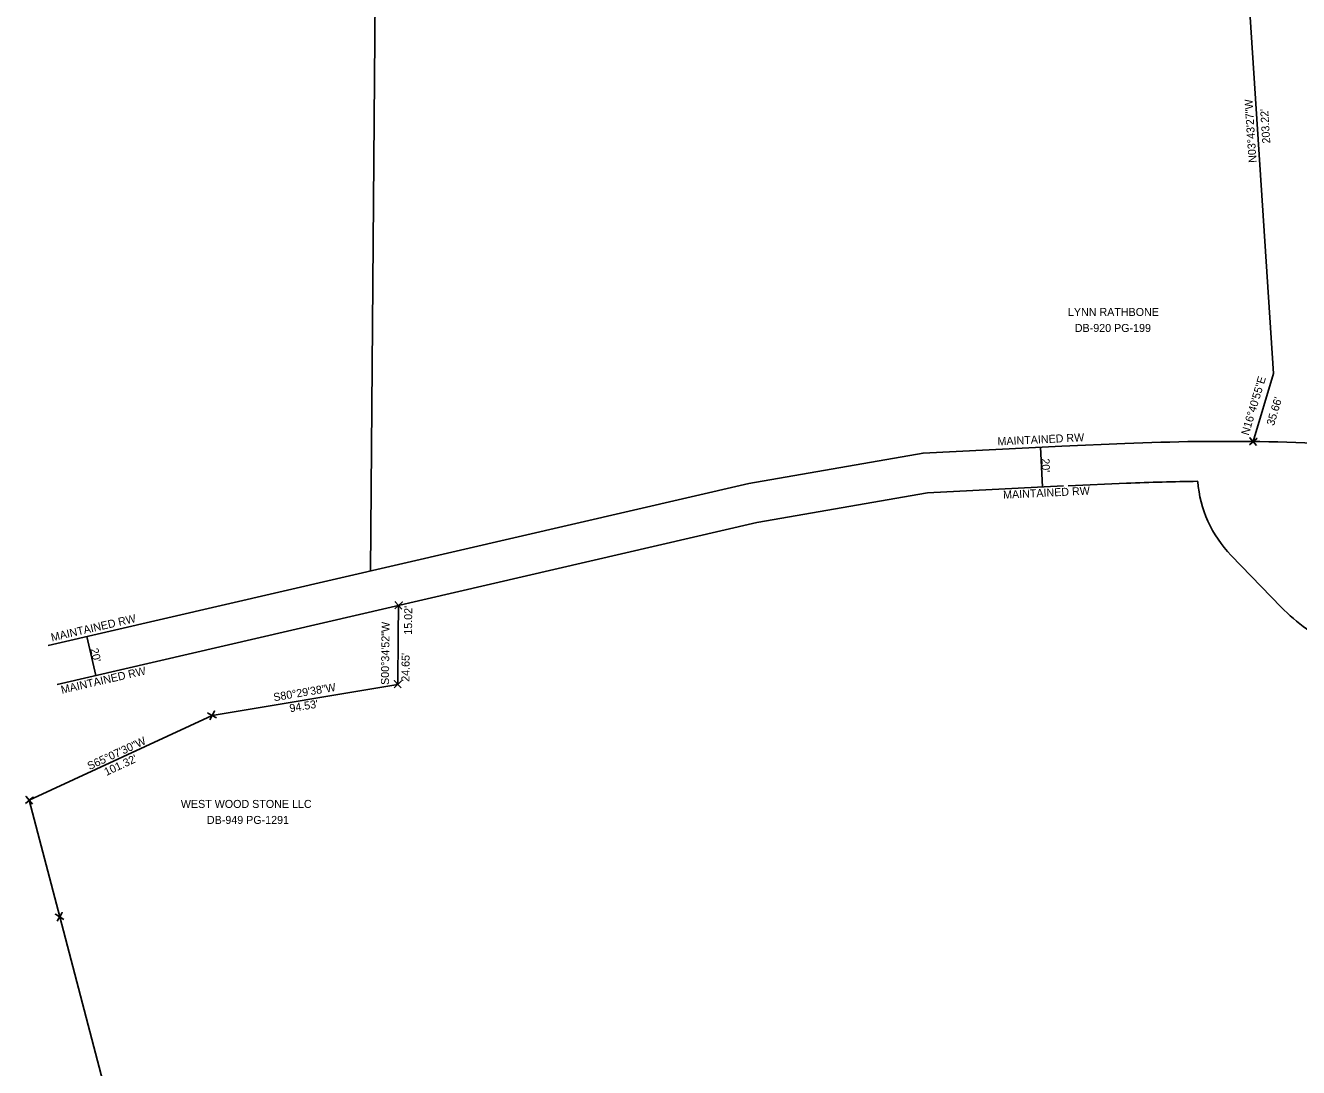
# Model space of a CAD drawing. Extents: x 831731 to 833706, y 722402 to 726085.
# Drawn here: x 831731 to 832371, y 723991 to 724515 of the extents above; entities that cross this region are included whole.
import ezdxf

# ---------------------------------------------------------------- set-up
doc = ezdxf.new("R2010")
doc.units = 0
for name, color, linetype in [('Exist Property Corner CELL', 7, 'Continuous'), ('Exist Property Line', 7, 'Continuous'), ('Exist Property Text', 7, 'Continuous'), ('Exist Right of Way Line', 7, 'Continuous'), ('Exist Right of Way Text', 7, 'Continuous'), ('Exist Right of Way Width CELL', 7, 'Continuous')]:
    doc.layers.add(name, color=color, linetype=linetype)

msp = doc.modelspace()

# ---------------------------------------------------------------- linework, layer by layer
at = {"layer": 'Exist Property Corner CELL'}
for p, q in [((832347.96, 724305.9), (832347.96, 724305.9)), ((831918.67, 724223.59), (831918.67, 724223.59)), ((831918.27, 724183.92), (831918.27, 724183.92)), ((831825.04, 724168.31), (831825.04, 724168.31)), ((831733.12, 724125.69), (831733.12, 724125.69)), ((831748.43, 724067.15), (831748.43, 724067.15))]:
    msp.add_line(p, q, dxfattribs=at)
for points in [[(832346.06, 724304.28), (832349.87, 724307.51), (832347.96, 724305.9), (832346.35, 724307.8), (832349.58, 724303.99)], [(831916.82, 724221.91), (831920.52, 724225.27), (831918.67, 724223.59), (831916.99, 724225.44), (831920.35, 724221.74)], [(831916.44, 724182.22), (831920.1, 724185.62), (831918.27, 724183.92), (831916.57, 724185.75), (831919.97, 724182.09)], [(831823.87, 724166.1), (831826.2, 724170.52), (831825.04, 724168.31), (831822.83, 724169.47), (831827.25, 724167.14)], [(831731.21, 724124.07), (831735.02, 724127.31), (831733.12, 724125.69), (831731.49, 724127.59), (831734.74, 724123.79)], [(831747.14, 724065), (831749.71, 724069.29), (831748.43, 724067.15), (831746.29, 724068.43), (831750.57, 724065.86)]]:
    msp.add_lwpolyline(points, dxfattribs=at)
at = {"layer": 'Exist Property Line'}
for p, q in [((831909.37, 724844.45), (831904.52, 724240.84)), ((832358.2, 724340.06), (832345, 724542.84)), ((832347.96, 724305.9), (832358.2, 724340.06)), ((831918.67, 724223.59), (831918.52, 724208.57)), ((831918.52, 724208.57), (831918.27, 724183.92)), ((831918.27, 724183.92), (831825.04, 724168.31)), ((831825.04, 724168.31), (831733.12, 724125.69)), ((831733.12, 724125.69), (831748.43, 724067.15)), ((831748.43, 724067.15), (832019.98, 723028.96))]:
    msp.add_line(p, q, dxfattribs=at)
at = {"layer": 'Exist Right of Way Line'}
for p, q in [((832251.85, 724303.55), (832283.49, 724304.91)), ((832254.96, 724283.66), (832284.35, 724284.93)), ((832336.9, 724248.71), (832362.08, 724222.76))]:
    msp.add_line(p, q, dxfattribs=at)
for points in [[(832251.79, 724303.55), (832182.16, 724300.12), (832094.68, 724284.84), (831742.62, 724203.38)], [(832252.77, 724283.57), (832184.38, 724280.21), (832098.66, 724265.24), (831747.13, 724183.9)]]:
    msp.add_lwpolyline(points, dxfattribs=at)
for centre, radius, start, end in [((832333.41, 723145.99), 1160, 85.31667, 92.46667), ((832333.41, 723145.99), 1140, 90.66701, 92.46667), ((832379.96, 724290.49), 60, 184.38299, 224.13333), ((832430.27, 724288.91), 95, 224.13333, 244.41667)]:
    msp.add_arc(centre, radius, start, end, dxfattribs=at)
at = {"layer": 'Exist Right of Way Width CELL'}
for p, q in [((832242.08, 724283.08), (832241.16, 724303.06)), ((831766.63, 724188.41), (831762.12, 724207.89))]:
    msp.add_line(p, q, dxfattribs=at)
for points in [[(832241.16, 724303.02), (832241.17, 724302.77), (832241.04, 724302.99)], [(831762.12, 724207.89), (831762.18, 724207.64), (831762.01, 724207.83)]]:
    msp.add_lwpolyline(points, dxfattribs=at)

# ---------------------------------------------------------------- texts
at = {"layer": 'Exist Property Text'}
for s, rotation, p in [('N03°43\'27"W', 93.72403, (832349.7, 724446.06)), ("203.22'", 93.72403, (832356.6, 724455.75)), ('N16°40\'55"E', 73.31799, (832345.68, 724308.73)), ("35.66'", 73.31799, (832358.42, 724313.62)), ("15.02'", 89.41882, (831925.4, 724208.85)), ('S00°34\'52"W', 89.41882, (831913.81, 724183.61)), ("24.65'", 89.41882, (831924.09, 724185.2)), ('S80°29\'38"W', 9.50604, (831856.09, 724175.41)), ("94.53'", 9.50604, (831864.21, 724169.87)), ('S65°07\'30"W', 24.87493, (831763.41, 724140.81)), ("101.32'", 24.87493, (831771.88, 724137.87))]:
    msp.add_text(s, height=4.02, rotation=rotation, dxfattribs=at).set_placement(p)
for s, p in [('LYNN RATHBONE', (832254.92, 724368.99)), ('DB-920 PG-199', (832258.38, 724360.95)), ('WEST WOOD STONE LLC', (831809.27, 724121.84)), ('DB-949 PG-1291', (831822.37, 724113.8))]:
    msp.add_text(s, height=4.02, dxfattribs=at).set_placement(p)
at = {"layer": 'Exist Right of Way Text'}
for s, rotation, p in [('MAINTAINED RW', 2.81332, (832219.62, 724303.93)), ("20'", 272.02532, (832241.65, 724297.38)), ('MAINTAINED RW', 2.81332, (832222.45, 724277.12)), ('MAINTAINED RW', 13.02824, (831744.53, 724205.46)), ("20'", 282.79543, (831763.8, 724201.65)), ('MAINTAINED RW', 13.02824, (831749.54, 724179.16))]:
    msp.add_text(s, height=4.02, rotation=rotation, dxfattribs=at).set_placement(p)

doc.saveas('drawing.dxf')
